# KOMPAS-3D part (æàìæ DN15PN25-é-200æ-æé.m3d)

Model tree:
1. Объединить компоненты:1  (labels: СЕНС DN15PN25-В-200С)
2. Эскиз:1
3. Операция выдавливания:1
     Расстояние 1 = 14
4. Фаска:1
     Угол = 45; Длина 1 = 2; Длина 2 = 2

Referenced files in D:\Савин\!СЕНСОР\3D для заказчика\!Новый перечень\СЕНС\4. СЕНС-В-200С\DN15\: СЕНС DN15PN25-В-200С.a3d
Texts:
  СЕНС DN15PN25-В-200С-СВ
  ООО НПП Сенсор
  СЕНС DN15PN25-В-200С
